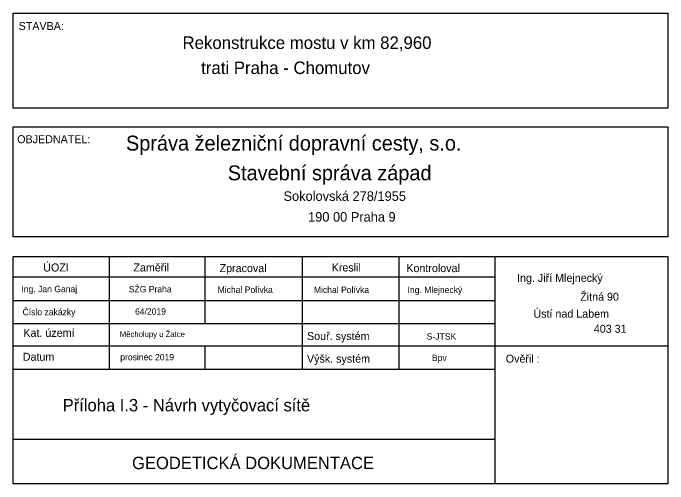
# Model space of a CAD drawing. Extents: x -879530 to -879371, y -1019242 to -1019127.
import ezdxf

# ---------------------------------------------------------------- set-up
doc = ezdxf.new("R2010")
doc.units = 0
doc.layers.add('LEGENDA', color=7, linetype='Continuous')
doc.layers.add('tabulka', color=7, linetype='Continuous')

msp = doc.modelspace()

# ---------------------------------------------------------------- linework, layer by layer
at = {"layer": 'tabulka'}
for p, q in [((-879530.09, -1019186.45), (-879371.44, -1019186.45)), ((-879506.8, -1019186.45), (-879506.8, -1019213.77)), ((-879483.66, -1019186.45), (-879483.66, -1019202.65)), ((-879460.06, -1019186.45), (-879460.06, -1019213.77)), ((-879436.61, -1019186.45), (-879436.61, -1019213.77)), ((-879413.31, -1019241.58), (-879413.31, -1019186.45)), ((-879530.09, -1019191.36), (-879413.31, -1019191.36)), ((-879530.09, -1019197.07), (-879413.31, -1019197.07)), ((-879530.09, -1019202.65), (-879413.31, -1019202.65)), ((-879530.09, -1019208.07), (-879371.44, -1019208.07)), ((-879483.66, -1019208.07), (-879483.66, -1019213.77)), ((-879530.09, -1019213.77), (-879413.31, -1019213.77)), ((-879530.09, -1019230.76), (-879413.31, -1019230.76))]:
    msp.add_line(p, q, dxfattribs=at)
for points in [[(-879530.09, -1019127.36), (-879371.44, -1019127.36), (-879371.44, -1019150.43), (-879530.09, -1019150.43)], [(-879530.09, -1019154.95), (-879371.44, -1019154.95), (-879371.44, -1019181.64), (-879530.09, -1019181.64)]]:
    msp.add_lwpolyline(points, close=True, dxfattribs=at)
msp.add_lwpolyline([(-879371.44, -1019186.45), (-879371.44, -1019241.58), (-879530.09, -1019241.58), (-879530.09, -1019186.45)], dxfattribs=at)

# ---------------------------------------------------------------- texts
at = {"layer": 'LEGENDA'}
for s, p in [('Rekonstrukce mostu v km 82,960', (-879489.04, -1019136.07)), ('    trati Praha - Chomutov', (-879489.04, -1019142.15))]:
    msp.add_text(s, height=3.04, dxfattribs=at).set_placement(p)
at = {"layer": 'tabulka'}
for s, height, p in [('STAVBA:', 1.94, (-879528.75, -1019131.47)), ('OBJEDNATEL:', 1.94, (-879529.1, -1019158.93)), ('Správa železniční dopravní cesty, s.o.', 3.61, (-879502.75, -1019160.71)), ('Stavební správa západ', 3.61, (-879478.08, -1019167.93)), ('Sokolovská 278/1955', 2.32, (-879464.57, -1019172.92)), ('190 00 Praha 9', 2.32, (-879458.62, -1019177.96)), ('ÚOZI', 1.94, (-879522.79, -1019190.05)), ('Zaměřil', 1.94, (-879500.95, -1019190.05)), ('Zpracoval', 1.94, (-879480.06, -1019190.2)), ('Kreslil', 1.94, (-879452.9, -1019190.05)), ('Kontroloval', 1.94, (-879434.81, -1019190.2)), ('Ing. Jiří Mlejnecký', 1.94, (-879407.98, -1019192.57)), ('Ing. Jan Ganaj', 1.552, (-879528.08, -1019195.08)), ('SŽG Praha', 1.552, (-879502.06, -1019195.11)), ('Michal Polívka', 1.552, (-879480.54, -1019195.23)), ('Michal Polívka', 1.552, (-879457.21, -1019195.27)), ('Ing. Mlejnecký', 1.552, (-879434.52, -1019195.27)), ('Žitná 90', 1.94, (-879392.68, -1019197.14)), ('Číslo zakázky', 1.552, (-879527.79, -1019200.66)), ('64/2019', 1.552, (-879500.55, -1019200.52)), ('Ústí nad Labem', 1.94, (-879404.02, -1019201.26)), ('403 31', 1.94, (-879389.39, -1019204.92)), ('Kat. území', 1.94, (-879527.6, -1019205.91)), ('Měcholupy u Žatce', 1.3968, (-879504.24, -1019205.95)), ('Souř. systém', 1.94, (-879458.87, -1019206.68)), ('S-JTSK', 1.552, (-879429.88, -1019206.59)), ('Datum', 1.94, (-879527.74, -1019211.71)), ('prosinec 2019', 1.552, (-879504.13, -1019211.6)), ('Výšk. systém', 1.94, (-879458.89, -1019212.17)), ('Bpv', 1.552, (-879428.62, -1019211.78)), ('Ověřil :', 1.94, (-879410.72, -1019212.17)), ('Příloha I.3 - Návrh vytyčovací sítě', 3, (-879518.08, -1019223.98)), ('GEODETICKÁ DOKUMENTACE ', 3, (-879501.27, -1019237.99))]:
    msp.add_text(s, height=height, dxfattribs=at).set_placement(p)

doc.saveas('drawing.dxf')
